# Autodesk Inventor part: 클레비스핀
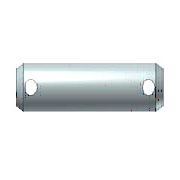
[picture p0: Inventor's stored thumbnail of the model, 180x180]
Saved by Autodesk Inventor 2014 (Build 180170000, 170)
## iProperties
IsCustomPart: 1
Created: 2012-02
Part Number: 클레비스핀
Material: 강철
Description: 머리가 없는 클레비스 핀 B
Document SubType Name: Modeling
Standard: ISO 2340
Designer: mduedu
Standard Revision: Second edition 1986-11-01
Standards Organization: ISO
Language: ko-KR
Size Designation: B - 8 x 45
Categories: <MemberInstance><Categories><Category DisplayName="조임쇠" InternalName="e4da775c-781d-43d5-af7c-5136215cf5a6" Mnemonic="FSTN"><Category DisplayName="핀" InternalNa
Density: 7.85 g/cm^3
Appearance: 반광택
Author: mduedu
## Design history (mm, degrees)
sketch "스케치1"
  geometry: L1 (-4.5, 0)-(-4.5, 4); L2 (-4.5, 4)-(35.5, 4); L3 (35.5, 4)-(35.5, 0); L4 (-4.5, 0)-(35.5, 0); L5 (0, -2)-(0, 5) reference; L6 (-13.5, 0)-(49.5, 0) reference; C1 r 1 at (-1, 0); C2 r 1 at (32, 0)
  constraints: 8 end point, 2 centre point, 2 perpendicular, 2 point on line, 1 collinear, 1 parallel, 1 tangent, 1 vertical
  dimensions: "d0" = 8 diameter of L2 L4 (= NND); "d1" = 40 distance of L1.end L2.end (= NLG); "d2" = 3.5 distance from line of L1 C1.centre (= DIST1); "d3" = 3.5 distance from line of L3 C2.centre (= DIST2); "d4" = 2 diameter of C1 (= BOR1); "d5" = 2 diameter of C2 (= BOR2)
revolve "본체" stored, may be unused: angle "d7" = 90 deg
extrude "구멍1" cut sketch "스케치1" taper "d6" = 0 deg; stored distance "d8" = 10
extrude "구멍2" cut sketch "스케치1" taper "d13" = 0 deg; stored distance "d14" = 10
workaxis "Work Axis1"
workaxis "Work Axis2"
workplane "Work Plane1"
node "작업 평면5"
body "Solid1"
chamfer "모따기2" distance "d9" = 2 (= PHH2); stored, may be unused: angle "d10" = 30 deg (= FAWI2), second distance "d40" = 2 (= PHH2)
chamfer "모따기1" distance "d11" = 2 (= PHH1); stored, may be unused: angle "d12" = 30 deg (= FAWI1), second distance "d41" = 2 (= PHH1)
other parameters: "NLG" = 40 [user parameter; used in 1 equation term], "NND" = 8 [user parameter; used in 1 equation term], "PHH1" = 2 [user parameter; used in 3 equation terms], "PHH2" = 2 (= PHH1) [user parameter; used in 2 equation terms], "FAWI1" = 30 deg [user parameter; used in 1 equation term], "FAWI2" = 30 deg [user parameter; used in 1 equation term], "DIST1" = 3.5 [user parameter; used in 4 equation terms], "DIST2" = 3.5 (= DIST1) [user parameter; used in 1 equation term], "BOR1" = 2 [user parameter; used in 4 equation terms], "BOR2" = 2 (= BOR1) [user parameter; used in 1 equation term], "d15" = 0, "d42" = 0, "d43" = 0, "d44" = -4.5 (= -0.5 x BOR1 - DIST1), "d45" = -4.5 (= -0.5 x BOR1 - DIST1), "d47" = 0, "d48" = 0, "d49" = 0, "d50" = 0, "d51" = 0, "d52" = 0
